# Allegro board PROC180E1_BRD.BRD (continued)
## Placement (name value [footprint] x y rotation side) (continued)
R83  4.7K  [RES0201_0-5]  121.76 149.17 180 top
R84  0E  [RES0201_0-5]  94.58 148.86 180 top
R85  4.7K  [RES0201_0-5]  121.76 148.22 0 top
R86  0E  [RES0805_0-75]  29.53 148.16 0 top
R87  0E  [RES0201_0-5]  73.69 147.95 270 top
R88  59E_1%  [RES0402_0-5]  36.77 147.8 270 top
R89  0E  [RES0201_0-5]  120.92 147.23 180 top
R90  10K  [RES0402_0-5]  92.73 147.17 180 top
R91  10K  [RES0201_0-5]  30.21 146.57 180 top
R92  0E  [RES0603_0-75]  78.61 146.43 0 top
R93  59E_1%  [RES0402_0-5]  36.77 145.55 270 top
R94  10K  [RES0201_0-5]  80.35 143.84 180 top
R95  0E  [RES0201_0-5]  120.24 143.24 90 top
R96  100K  [RES0201_0-5]  40.88 143.04 0 top
R97  0E  [RES0603_0-75]  118.92 142.49 270 top
R98  10K  [RES0201_0-5]  84.24 142.24 270 top
R99  0E  [RES0201_0-5]  79.02 141.96 270 top
R100  0E  [RES0201_0-5]  80.25 141.96 90 top
R101  0E  [RES0201_0-5]  81.14 141.96 90 top
R102  0E  [RES0402_0-5]  40.68 141.72 180 top
R103  10K  [RES0402_0-5]  28.28 141.3 90 top
R104  0E  [RES0201_0-5]  72.54 140.22 270 top
R105  0E  [RES0201_0-5]  73.43 140.22 270 top
R106  10K  [RES0201_0-5]  108.51 138.55 270 top
R107  10K  [RES0201_0-5]  104.22 138.39 180 top
R108  0E  [RES0201_0-5]  109.46 137.76 90 top
R109  0E  [RES0201_0-5]  78.52 136.07 270 top
R110  500E_1%  [RES0402_0-5]  79.78 135.94 270 top
R111  100K_1%  [RES0402_0-5]  81.05 135.94 270 top
R112  10K  [RES0201_0-5]  94.05 134.35 0 top
R113  28K_1%  [RES0402_0-5]  80.45 134.25 180 top
R114  10K  [RES0402_0-5]  57.41 130.66 180 top
R115  100K  [RES0201_0-5]  61.32 127.63 180 top
R116  0E  [RES0201_0-5]  60.72 126.5 0 top
R117  10K  [RES0201_0-5]  65.87 124.88 270 top
R118  4.7K  [RES0201_0-5]  109.22 124.29 90 top
R119  4.7K  [RES0201_0-5]  110.49 124.29 90 top
R120  2.2K  [RES0201_0-5]  41.96 123.04 180 top
R121  0E  [RES0201_0-5]  95.1 121.5 0 top
R122  10K  [RES0201_0-5]  96.31 121.22 270 top
R123  10K  [RES0201_0-5]  74.57 121.03 90 top
R124  10K  [RES0201_0-5]  101.21 119.31 270 top
R125  0E  [RES0201_0-5]  74.57 118.94 270 top
R126  1K  [RES0201_0-5]  91.49 117.43 90 top
R127  1K  [RES0201_0-5]  92.76 117.43 90 top
R128  1K  [RES0201_0-5]  94.03 117.43 90 top
R129  1K  [RES0201_0-5]  95.3 117.43 90 top
R130  1K  [RES0201_0-5]  96.57 117.43 90 top
R131  1K  [RES0201_0-5]  97.84 117.43 90 top
R132  1K  [RES0201_0-5]  99.11 117.43 90 top
R133  1K  [RES0201_0-5]  100.38 117.43 90 top
R134  1K  [RES0201_0-5]  104 117.43 90 top
R135  1K  [RES0201_0-5]  105.27 117.43 90 top
R136  1K  [RES0201_0-5]  106.54 117.43 90 top
R137  1K  [RES0201_0-5]  107.81 117.43 90 top
R138  1K  [RES0201_0-5]  109.08 117.43 90 top
R139  1K  [RES0201_0-5]  110.35 117.43 90 top
R140  1K  [RES0201_0-5]  111.62 117.43 90 top
R141  1K  [RES0201_0-5]  112.89 117.43 90 top
R142  10K  [RES0201_0-5]  75.83 113.62 180 top
R143  10K  [RES0201_0-5]  69.87 111.84 180 top
R144  10K  [RES0201_0-5]  57.19 108.43 0 top
R145  100K  [RES0201_0-5]  91.49 105.99 270 top
R146  100K  [RES0201_0-5]  92.76 105.99 270 top
R147  100K  [RES0201_0-5]  94.03 105.99 270 top
R148  100K  [RES0201_0-5]  95.3 105.99 270 top
R149  100K  [RES0201_0-5]  96.57 105.99 270 top
R150  100K  [RES0201_0-5]  97.84 105.99 270 top
R151  100K  [RES0201_0-5]  99.11 105.99 270 top
R152  100K  [RES0201_0-5]  100.38 105.99 270 top
R153  100K  [RES0201_0-5]  104 105.99 270 top
R154  100K  [RES0201_0-5]  105.27 105.99 270 top
R155  100K  [RES0201_0-5]  106.54 105.99 270 top
R156  100K  [RES0201_0-5]  107.81 105.99 270 top
R157  100K  [RES0201_0-5]  109.08 105.99 270 top
R158  100K  [RES0201_0-5]  110.35 105.99 270 top
R159  100K  [RES0201_0-5]  111.62 105.99 270 top
R160  100K  [RES0201_0-5]  112.89 105.99 270 top
R161  10K  [RES0201_0-5]  95.45 104.42 180 top
R162  10K  [RES0201_0-5]  83.61 104.04 180 top
R163  0E  [RES0201_0-5]  87.2 101.01 90 top
R164  10K  [RES0402_0-5]  51.31 100.68 90 top
R165  0E  [RES0201_0-5]  75.12 99.73 0 top
R166  10K  [RES0201_0-5]  44.91 99.09 90 top
R167  0E  [RES0402_0-5]  65.65 98.89 90 top
R168  0E  [RES0402_0-5]  67.18 98.89 90 top
R169  0E  [RES0402_0-5]  68.7 98.89 90 top
R170  0E  [RES0201_0-5]  49.11 98.71 270 top
R171  0E  [RES0402_0-5]  55.22 98.5 90 top
R172  22E  [RES0402_0-5]  56.74 98.5 90 top
R173  0E  [RES0402_0-5]  58.27 98.5 90 top
R174  22E  [RES0402_0-5]  59.79 98.5 90 top
R175  22E  [RES0201_0-5]  48.83 98.43 0 top
R176  0E  [RES0402_0-5]  77.22 97.62 90 top
R177  0E  [RES0402_0-5]  78.74 97.62 90 top
R178  22E  [RES0402_0-5]  80.27 97.62 270 top
R179  22E  [RES0402_0-5]  81.79 97.62 270 top
R180  220E  [RES0402_0-5]  118.58 97.17 180 top
R181  0E  [RES0201_0-5]  23.27 97.12 0 top
R182  0E  [RES0402_0-5]  64.94 96.86 90 top
R183  0E  [RES0402_0-5]  66.46 96.86 90 top
R184  22E  [RES0402_0-5]  67.99 96.86 90 top
R185  22E  [RES0402_0-5]  70.38 96.65 90 top
R186  0E  [RES0402_0-5]  56.01 96.53 90 top
R187  0E  [RES0402_0-5]  57.53 96.53 90 top
R188  0E  [RES0402_0-5]  59.06 96.53 90 top
R189  0E  [RES0402_0-5]  60.58 96.53 90 top
R190  0E  [RES0402_0-5]  76.48 95.58 90 top
R191  0E  [RES0402_0-5]  78 95.58 90 top
R192  0E  [RES0402_0-5]  79.53 95.58 90 top
R193  0E  [RES0402_0-5]  81.05 95.58 90 top
R194  0E  [RES0201_0-5]  22.28 95.25 90 top
R195  22E  [RES0402_0-5]  46.26 95.22 90 top
R196  10K  [RES0201_0-5]  27.15 95.1 0 top
R197  0E  [RES0402_0-5]  75.51 94.43 270 top
R198  4.7K  [RES0201_0-5]  62.97 94.39 0 top
R199  33E  [RES0402_0-5]  43.56 94.17 180 top
R200  4.7K  [RES0201_0-5]  47.15 94.07 270 top
R201  0E  [RES0402_0-5]  86.44 94.06 90 top
R202  10K  [RES0201_0-5]  68.78 94.01 90 top
R203  10K  [RES0201_0-5]  123.2 93.82 270 top
R204  0E  [RES0201_0-5]  45.98 93.79 180 top
R205  0E  [RES0201_0-5]  70.96 93.74 270 top
R206  0E  [RES0201_0-5]  71.93 93.74 270 top
R207  0E  [RES0201_0-5]  68.78 93.45 270 top
R208  59E_1%  [RES0402_0-5]  33.79 93.33 270 top
R209  0E  [RES0402_0-5]  89.15 92.99 90 top
R210  62E_1%  [RES0402_0-5]  53.06 92.79 0 top
R211  10K  [RES0201_0-5]  103.45 92.71 270 top
R212  10K  [RES0201_0-5]  104.21 92.71 270 top
R213  0E  [RES0402_0-5]  122.47 92.38 180 top
R214  1K  [RES0201_0-5]  91.06 91.65 270 top
R215  59E_1%  [RES0402_0-5]  33.79 91.2 270 top
R216  22E  [RES0201_0-5]  50.26 90.69 180 top
R217  1K  [RES0201_0-5]  91.06 89.82 90 top
R218  4.87K_1%  [RES0402_0-5]  122.05 89.75 90 top
R219  0E  [RES0201_0-5]  106.79 89.39 0 top
R220  10K  [RES0201_0-5]  104.7 89.23 180 top
R221  0E  [RES0201_0-5]  116.3 88.99 180 top
R222  100K  [RES0201_0-5]  36.43 88.62 0 top
R223  0E  [RES0402_0-5]  38.55 88.62 0 top
R224  0E  [RES0201_0-5]  106.79 88.5 0 top
R225  10K  [RES0201_0-5]  103.46 88.26 180 top
R226  10K  [RES0201_0-5]  93.78 88.17 180 top
R227  0E  [RES0201_0-5]  116.3 88.1 180 top
R228  0E  [RES0201_0-5]  89.11 87.73 0 top
R229  1K_1%  [RES0402_0-5]  118.19 87.66 270 top
R230  1K_1%  [RES0402_0-5]  119.46 87.66 270 top
R231  1K_1%  [RES0402_0-5]  120.73 87.66 270 top
R232  1K_1%  [RES0402_0-5]  122 87.66 270 top
R233  0E  [RES0201_0-5]  106.79 87.61 0 top
R234  62E_1%  [RES0402_0-5]  53.96 87.46 0 top
R235  0E  [RES0201_0-5]  116.3 87.21 180 top
R236  4.7K  [RES0201_0-5]  127.8 86.78 270 top
R237  4.7K  [RES0201_0-5]  128.56 86.78 270 top
R238  4.7K  [RES0201_0-5]  100.43 86.64 90 top
R239  0E  [RES0201_0-5]  88.49 85.72 270 top
R240  10K  [RES0201_0-5]  40.63 85.32 270 top
R241  4.7K  [RES0201_0-5]  134.75 85.23 90 top
R242  10K  [RES0201_0-5]  99.84 85.1 0 top
R243  0E  [RES0402_0-5]  53.27 84.63 0 top
R244  10K  [RES0201_0-5]  47.35 83.57 90 top
R245  100K  [RES0402_0-5]  46.28 83.36 90 top
R246  49.9E_1%  [RES0402_0-5]  114.55 83.13 180 top
R247  10K  [RES0201_0-5]  94.65 83.11 180 top
R248  10K  [RES0201_0-5]  25.41 81.49 0 top
R249  0E  [RES0201_0-5]  59.07 81.16 270 top
R250  0E  [RES0201_0-5]  35.29 81.14 180 top
R251  0.01E_1%  [RES_KRL3216T4_1206-4_0-7]  49.35 81.13 90 top
R252  0E  [RES0201_0-5]  58.79 80.94 0 top
R253  0E  [RES0201_0-5]  58.79 79.84 0 top
R254  0E  [RES0201_0-5]  59.07 79.56 90 top
R255  100K_1%  [RES0402_0-5]  42.22 79.51 180 top
R256  62E_1%  [RES0402_0-5]  23.74 79.46 0 top
R257  0E  [RES0402_0-5]  44.16 79.15 0 top
R258  182K_1%  [RES0402_0-5]  40.53 79.02 270 top
R259  4.7K  [RES0201_0-5]  22.88 78.44 0 top
R260  220E  [RES0402_0-5]  23.2 76.87 180 top
R261  0E  [RES0201_0-5]  59.75 76.6 270 top
R262  10K  [RES0201_0-5]  92.87 76.48 0 top
R263  10K  [RES0201_0-5]  92.87 75.72 0 top
R264  10K  [RES0201_0-5]  92.87 74.95 0 top
R265  0.001E_1%  [RES_CST0612_0612-4_0-9]  44.43 74.3 270 top
R266  10K  [RES0201_0-5]  92.87 74.19 0 top
R267  10K  [RES0201_0-5]  92.87 73.43 0 top
R268  10K  [RES0201_0-5]  32.34 72.73 270 top
R269  10K  [RES0201_0-5]  92.87 72.67 0 top
R270  10K  [RES0201_0-5]  92.87 71.91 0 top
R271  0E  [RES0201_0-5]  115.92 71.79 180 top
R272  1K  [RES0402_0-5]  25.8 71.76 270 top
R273  0E  [RES0402_0-5]  62.49 71.57 90 top
R274  0E  [RES0201_0-5]  32.34 71.31 90 top
R275  10K  [RES0201_0-5]  92.87 71.14 0 top
R276  220E  [RES0402_0-5]  135.3 71.01 270 top
R277  1K  [RES0402_0-5]  111.87 70.45 180 top
R278  10K  [RES0201_0-5]  113.58 70.45 180 top
R279  10K  [RES0201_0-5]  31.57 69.98 0 top
R280  10K  [RES0201_0-5]  115.71 68.66 180 top
R281  0E  [RES0201_0-5]  54.94 68.49 270 top
R282  10K  [RES0201_0-5]  55.73 68.49 270 top
R283  0E  [RES0201_0-5]  112.17 68.37 0 top
R284  62E_1%  [RES0402_0-5]  33.27 67.93 90 top
R285  10K  [RES0201_0-5]  112.17 67.61 180 top
R286  0E  [RES0201_0-5]  38.84 67.6 90 top
R287  220E  [RES0402_0-5]  132.7 67.24 270 top
R288  10K  [RES0201_0-5]  57.09 67.08 0 top
R289  20K_1%  [RES0402_0-5]  134.48 67.04 0 top
R290  0E  [RES0201_0-5]  55.09 66.8 270 top
R291  10K  [RES0201_0-5]  55.88 66.8 270 top
R292  220E  [RES0402_0-5]  37.76 66.41 0 top
R293  0E  [RES0201_0-5]  29.35 65.96 0 top
R294  0E  [RES0201_0-5]  43.51 65.79 0 top
R295  30K  [RES0402_0-5]  134.48 65.77 180 top
R296  0E  [RES0201_0-5]  41.48 65.34 0 top
R297  0E  [RES0201_0-5]  42.67 64.61 270 top
R298  2K_1%  [RES0402_0-5]  34.68 64.52 90 top
R299  0E  [RES0201_0-5]  55.63 64.46 90 top
R300  0E  [RES0201_0-5]  56.41 64.46 90 top
R301  4.7K  [RES0201_0-5]  38.47 64.36 270 top
R302  10K  [RES0402_0-5]  20.69 64.2 90 top
R303  1.3K_1%  [RES0402_0-5]  28.96 64.06 180 top
R304  0E  [RES0603_0-75]  61.56 64.03 180 top
R305  0E  [RES0201_0-5]  36.83 63.64 0 top
R306  51K_1%  [RES0402_0-5]  116.42 63.25 0 top
R307  0E  [RES0201_0-5]  41.24 63.14 90 top
R308  1K_1%  [RES0402_0-5]  35.78 62.53 270 top
R309  100K  [RES0402_0-5]  20.09 62.4 180 top
R310  0E  [RES0402_0-5]  55.51 62.36 270 top
R311  0E  [RES0402_0-5]  56.66 62.36 270 top
R312  240E_1%  [RES0201_0-5]  66.97 62.03 0 top
R313  30K_1%  [RES0402_0-5]  116.42 61.98 180 top
R314  0E  [RES0201_0-5]  120.42 60.56 90 top
R315  240E_1%  [RES0201_0-5]  66.97 59.63 0 top
R316  0.01E_1%  [RES_KRL3216T4_1206-4_0-7]  56.18 59.2 0 top
R317  0E  [RES0201_0-5]  48.44 58.81 180 top
R318  10K  [RES0402_0-5]  26.62 58.34 180 top
R319  0E  [RES0201_0-5]  59.89 56.26 90 top
R320  10K  [RES0201_0-5]  60.91 56.26 270 top
R321  10K  [RES0201_0-5]  28.14 53.12 90 top
R322  4.7K  [RES0201_0-5]  35.69 52.75 180 top
R323  2.2K  [RES0201_0-5]  29.16 52.56 90 top
R324  220E  [RES0402_0-5]  34.39 88.62 0 top
R325  10K  [RES0201_0-5]  71.14 51.98 0 top
R326  4.7K  [RES0201_0-5]  35.69 51.92 180 top
R327  0.001E_1%  [RES_CST0612_0612-4_0-9]  57.15 51.75 0 top
R328  10K  [RES0201_0-5]  28.44 51.54 0 top
R329  10K  [RES0201_0-5]  80.97 51.22 0 top
R330  220E  [RES0402_0-5]  30.92 50.49 0 top
R331  0E  [RES0402_0-5]  48.97 50.29 180 top
R332  0E  [RES0402_0-5]  74.29 50.27 90 top
R333  10K  [RES0201_0-5]  28.14 50.07 180 top
R334  0.01E_1%  [RES_KRL3216T4_1206-4_0-7]  45.08 49.68 270 top
R335  0E  [RES0402_0-5]  48.97 49.02 180 top
R336  22E  [RES0201_0-5]  78.09 48.58 0 top
R337  0E  [RES0201_0-5]  78.09 47.82 0 top
R338  0E  [RES0402_0-5]  85.25 47.62 180 top
R339  10K  [RES0201_0-5]  69.44 47.24 0 top
R340  0E  [RES0402_0-5]  88.07 47 180 top
R341  1K_1%  [RES0402_0-5]  122.28 46.89 0 top
R342  10K  [RES0201_0-5]  84.77 46.57 180 top
R343  1.5K  [RES0201_0-5]  86.32 46.57 180 top
R344  2.2K  [RES0201_0-5]  116 46.49 0 top
R345  0E  [RES0201_0-5]  119.68 46.49 0 top
R346  0E  [RES0201_0-5]  117.52 46.48 0 top
R347  100K  [RES0201_0-5]  128.93 46.48 270 bottom
R348  10K  [RES0201_0-5]  70.72 46.33 90 top
R349  22E  [RES0201_0-5]  69.56 46.32 90 top
R350  0E  [RES0402_0-5]  72.76 46.25 90 top
R351  1.5K  [RES0201_0-5]  119.68 45.6 180 top
R352  0E  [RES0201_0-5]  118.51 45.29 270 top
R353  100K  [RES0201_0-5]  87.64 45 270 top
R354  100K  [RES0201_0-5]  121.02 44.99 270 top
R355  1K_1%  [RES0402_0-5]  89.46 44.56 270 top
R356  10K  [RES0201_0-5]  118.79 44.03 180 top
R357  10K  [RES0201_0-5]  23.04 42.28 0 top
R358  22E  [RES0201_0-5]  67.66 37.43 180 top
R359  22E  [RES0201_0-5]  71.11 37.11 270 top
R360  100K  [RES0201_0-5]  73.28 36.76 270 top
R361  4.7K  [RES0201_0-5]  28.19 34.68 180 top
R362  10K  [RES0201_0-5]  67.82 31.96 0 top
R363  10K  [RES0201_0-5]  69.53 31.96 180 top
R364  0E  [RES0201_0-5]  66.52 31.36 270 top
R365  10K  [RES0201_0-5]  71.28 31.16 90 top
R366  0E  [RES0201_0-5]  70.13 30.98 180 top
R367  10K  [RES0201_0-5]  67.32 30.8 270 top
R368  10K  [RES0201_0-5]  45.21 30.41 270 top
R369  10K  [RES0201_0-5]  45.98 30.41 90 top
R370  10K  [RES0201_0-5]  46.94 30.41 90 top
R371  10K  [RES0201_0-5]  51.17 30.37 0 top
R372  10K  [RES0201_0-5]  67.32 29.33 270 top
R373  10K  [RES0201_0-5]  68.72 28.81 180 top
R374  10K  [RES0201_0-5]  43.91 28.51 270 top
R375  10K  [RES0201_0-5]  63.82 27.9 180 top
R376  0E  [RES0201_0-5]  68.73 27.84 180 top
R377  0E  [RES0201_0-5]  70.17 27.84 0 top
R378  10K  [RES0201_0-5]  35.34 27.09 90 top
R379  0E  [RES0201_0-5]  58.79 26.02 270 top
R380  10K  [RES0201_0-5]  48.56 25.62 270 top
R381  10K  [RES0201_0-5]  26.52 25.07 90 top
R382  0E  [RES0201_0-5]  25.68 24.91 90 top
R383  10K  [RES0201_0-5]  58.51 24.85 180 top
R384  16.5K_1%  [RES0402_0-5]  69.69 24.34 0 top
R385  0E  [RES0805_0-75]  12.55 24.33 90 top
R386  0E  [RES0201_0-5]  25.95 23.8 0 top
R387  10K  [RES0201_0-5]  46.15 23.75 180 top
R388  0E  [RES0201_0-5]  47.2 23.47 270 top
R389  3.48K_1%  [RES0201_0-5]  69.9 22.95 180 top
R390  0E  [RES0201_0-5]  24.41 22.56 0 top
R391  130K_1%  [RES0402_0-5]  47.74 21.36 180 top
R392  680K_1%  [RES0402_0-5]  49.45 20.87 90 top
R393  0E  [RES0402_0-5]  64.65 20.11 270 top
R394  0E  [RES0402_0-5]  65.5 20.11 270 top
R395  0E  [RES0603_0-75]  29.41 19.14 0 top
R396  10K  [RES0201_0-5]  57.2 18.68 270 top
R397  470E  [RES0402_0-5]  35.15 15.24 90 top
R398  16.5K_1%  [RES0402_0-5]  53.31 12.95 270 top
R399  0E  [RES0402_0-5]  48.97 12.17 270 top
R400  0E  [RES0402_0-5]  49.82 12.17 270 top
R401  3.48K_1%  [RES0201_0-5]  53.03 11.57 180 top
R402  470E  [RES0402_0-5]  45.06 10.86 90 top
R403  0E  [RES0603_0-75]  42.58 8.45 90 top
R404  0E  [RES0603_0-75]  27.81 8.39 90 top
R405  4.3K  [RES0402_0-5]  90.34 179.93 270 bottom
R406  4.3K  [RES0402_0-5]  89.07 179.93 270 bottom
R407  4.3K  [RES0402_0-5]  86.5 179.93 270 bottom
R408  4.3K  [RES0402_0-5]  85.23 179.93 270 bottom
R409  4.3K  [RES0402_0-5]  73.2 179.93 270 bottom
R410  4.3K  [RES0402_0-5]  71.93 179.93 270 bottom
R411  4.3K  [RES0402_0-5]  69.36 179.93 270 bottom
R412  4.3K  [RES0402_0-5]  68.09 179.93 270 bottom
R413  10K  [RES0402_0-5]  80.85 174.25 180 bottom
R414  0E  [RES0201_0-5]  82.72 172.98 180 bottom
R415  10K  [RES0402_0-5]  76.16 171.56 270 bottom
R416  10K  [RES0402_0-5]  77.56 171.55 90 bottom
R417  10K  [RES0201_0-5]  47.17 168.06 0 bottom
R418  1K  [RES0402_0-5]  133.23 166.02 270 bottom
R419  1K  [RES0402_0-5]  131.94 166.02 90 bottom
R420  0E  [RES0201_0-5]  130.05 163.79 0 bottom
R421  0E  [RES0201_0-5]  112.53 163.78 0 bottom
R422  1K  [RES0402_0-5]  132.92 163.76 90 bottom
R423  1K  [RES0402_0-5]  131.61 163.76 270 bottom
R424  10K  [RES0201_0-5]  47.01 163.55 90 bottom
R425  10K  [RES0201_0-5]  45.06 163.08 90 bottom
R426  10K  [RES0201_0-5]  43.97 163.08 90 bottom
R427  0E  [RES0201_0-5]  52.99 162.99 180 bottom
R428  0E  [RES0201_0-5]  55.53 161.84 0 bottom
R429  10K  [RES0201_0-5]  105.57 161.26 180 bottom
R430  10K  [RES0201_0-5]  124.04 161.09 180 bottom
R431  0E  [RES0201_0-5]  75.21 159.73 180 bottom
R432  0E  [RES0201_0-5]  73.73 159.35 270 bottom
R433  0E  [RES0201_0-5]  74.01 159.07 180 bottom
R434  10K  [RES0201_0-5]  53.08 158.86 180 bottom
R435  0E  [RES0201_0-5]  73.73 158.79 90 bottom
R436  10K  [RES0402_0-5]  42.43 155.13 270 bottom
R437  2.2K  [RES0201_0-5]  108.85 151.32 0 bottom
R438  1K  [RES0201_0-5]  93.16 140.06 0 bottom
R439  10K  [RES0201_0-5]  93.16 137.52 180 bottom
R440  220E  [RES0402_0-5]  48.11 129 0 bottom
R441  0E  [RES0402_0-5]  53.89 125.16 180 bottom
R442  10K  [RES0201_0-5]  51.85 125.16 0 bottom
R443  10K  [RES0201_0-5]  81.22 123.25 90 bottom
R444  10K  [RES0201_0-5]  80.22 123.25 90 bottom
R445  10K  [RES0201_0-5]  79.22 123.25 90 bottom
R446  10K  [RES0201_0-5]  78.65 122 135 bottom
R447  10K  [RES0201_0-5]  82.79 121.62 90 bottom
R448  10K  [RES0201_0-5]  76.26 121.33 90 bottom
R449  10K  [RES0201_0-5]  77.49 120.98 180 bottom
R450  10K  [RES0201_0-5]  79.75 120.55 270 bottom
R451  10K  [RES0201_0-5]  82.79 120.39 90 bottom
R452  10K  [RES0201_0-5]  77.5 120.21 180 bottom
R453  22E  [RES0201_0-5]  79.98 119.41 0 bottom
R454  10K  [RES0201_0-5]  80.54 118.71 0 bottom
R455  10K  [RES0201_0-5]  70.33 118.1 180 bottom
R456  10K  [RES0201_0-5]  105.38 116.15 180 bottom
R457  10K  [RES0201_0-5]  110.49 115.98 0 bottom
R458  10K  [RES0201_0-5]  78.2 115.81 90 bottom
R459  10K  [RES0201_0-5]  77.31 115.81 270 bottom
R460  10K  [RES0201_0-5]  76.42 115.81 270 bottom
R461  10K  [RES0201_0-5]  102.57 114.67 0 bottom
R462  10K  [RES0201_0-5]  70.67 113.34 90 bottom
R463  0E  [RES0201_0-5]  73.28 110.33 180 bottom
R464  4.7K  [RES0201_0-5]  17.22 109.45 0 bottom
R465  4.7K  [RES0201_0-5]  17.25 108.66 0 bottom
R466  0E  [RES0402_0-5]  72.75 108.31 0 bottom
R467  10K  [RES0201_0-5]  59.64 108.1 180 bottom
R468  0E  [RES0201_0-5]  70.04 107.62 0 bottom
R469  10K  [RES0201_0-5]  59.09 107.34 0 bottom
R470  0E  [RES0402_0-5]  72.76 107.16 0 bottom
R471  10K  [RES0201_0-5]  59.09 106.42 0 bottom
R472  0E  [RES0201_0-5]  69.99 105.71 0 bottom
R473  10K  [RES0201_0-5]  59.09 105.53 0 bottom
R474  0E  [RES0201_0-5]  74.72 105.2 0 bottom
R475  0E  [RES0201_0-5]  74.72 104.54 0 bottom
R476  33E  [RES0201_0-5]  113.29 104.09 90 bottom
R477  0E  [RES0201_0-5]  76.97 104.05 90 bottom
R478  0E  [RES0201_0-5]  77.75 104.04 90 bottom
R479  0E  [RES0201_0-5]  78.53 104.03 90 bottom
R480  10K  [RES0201_0-5]  109.17 103.84 90 bottom
R481  0E  [RES0201_0-5]  66.31 103.81 90 bottom
R482  4.7K  [RES0201_0-5]  105.93 103.62 90 bottom
R483  33E  [RES0201_0-5]  118.11 103.56 270 bottom
R484  0E  [RES0201_0-5]  64.61 103.24 0 bottom
R485  10K  [RES0201_0-5]  114.99 103.01 90 bottom
R486  0E  [RES0201_0-5]  75.35 101.93 0 bottom
R487  100E_1%  [RES0402_0-5]  114.99 101.28 270 bottom
R488  10K  [RES0201_0-5]  69.16 100.18 90 bottom
R489  10K  [RES0201_0-5]  116.71 99.04 270 bottom
R490  0E  [RES0201_0-5]  115.51 99.04 270 bottom
R491  0E  [RES0402_0-5]  82.91 97.46 90 bottom
R492  0E  [RES0402_0-5]  81.34 97.46 90 bottom
R493  0E  [RES0402_0-5]  79.76 97.46 90 bottom
R494  0E  [RES0402_0-5]  78.19 97.46 90 bottom
R495  0E  [RES0402_0-5]  76.69 97.46 90 bottom
R496  0E  [RES0402_0-5]  67.18 96.8 180 bottom
R497  0E  [RES0402_0-5]  83.55 95.49 90 bottom
R498  0E  [RES0402_0-5]  82.03 95.49 90 bottom
R499  0E  [RES0402_0-5]  80.5 95.49 90 bottom
R500  0E  [RES0402_0-5]  78.98 95.49 90 bottom
R501  0E  [RES0402_0-5]  77.45 95.49 90 bottom
R502  0E  [RES0402_0-5]  75.93 95.49 90 bottom
R503  4.7K  [RES0201_0-5]  61.08 94.63 180 bottom
R504  1K  [RES0201_0-5]  75.28 93.1 90 bottom
R505  0E  [RES0201_0-5]  50.11 92.84 90 bottom
R506  0E  [RES0402_0-5]  72.3 90.88 90 bottom
R507  10K  [RES0201_0-5]  106.79 89.39 180 bottom
R508  4.7K  [RES0201_0-5]  59.71 89.39 0 bottom
R509  0E  [RES0201_0-5]  88.78 89.35 0 bottom
R510  10K  [RES0201_0-5]  114.08 89.28 180 bottom
R511  10K  [RES0201_0-5]  116.3 88.99 0 bottom
R512  10K  [RES0201_0-5]  108.99 88.9 0 bottom
R513  10K  [RES0201_0-5]  106.79 88.5 180 bottom
R514  22E  [RES0402_0-5]  59.71 88.5 180 bottom
R515  10K  [RES0201_0-5]  114.08 88.48 180 bottom
R516  10K  [RES0201_0-5]  116.3 88.1 0 bottom
R517  10K  [RES0201_0-5]  108.99 88.1 0 bottom
R518  0E  [RES0201_0-5]  87.12 87.92 0 bottom
R519  10K  [RES0201_0-5]  114.08 87.68 180 bottom
R520  1K_1%  [RES0402_0-5]  122 87.66 90 bottom
R521  1K_1%  [RES0402_0-5]  120.73 87.66 90 bottom
R522  1K_1%  [RES0402_0-5]  119.46 87.66 90 bottom
R523  1K_1%  [RES0402_0-5]  118.19 87.66 90 bottom
R524  10K  [RES0201_0-5]  106.79 87.61 180 bottom
R525  10K  [RES0201_0-5]  108.99 87.3 0 bottom
R526  10K  [RES0201_0-5]  116.3 87.21 0 bottom
R527  0E  [RES0201_0-5]  87.12 87.05 0 bottom
R528  0E  [RES0201_0-5]  87.12 86.28 0 bottom
R529  0E  [RES0201_0-5]  90.17 86 0 bottom
R530  0E  [RES0201_0-5]  87.12 85.43 0 bottom
R531  10K  [RES0201_0-5]  116.93 84.93 270 bottom
R532  10K  [RES0201_0-5]  28.47 84.16 0 bottom
R533  10K  [RES0201_0-5]  119.53 84.08 180 bottom
R534  10K  [RES0201_0-5]  118.39 84.07 90 bottom
R535  0E  [RES0201_0-5]  87.05 83.98 0 bottom
R536  10K  [RES0201_0-5]  117.21 83.89 0 bottom
R537  0E  [RES0201_0-5]  83.78 83.84 0 bottom
R538  0E  [RES0201_0-5]  66.91 83.74 180 bottom
R539  0E  [RES0402_0-5]  49.93 83.22 270 bottom
R540  0E  [RES0402_0-5]  48.79 83.22 270 bottom
R541  0E  [RES0402_0-5]  86.14 82.88 0 bottom
R542  22E  [RES0201_0-5]  67.18 82.82 0 bottom
R543  10K_1%  [RES0201_0-5]  58.69 82.71 0 bottom
R544  22E  [RES0201_0-5]  118.58 82.64 270 bottom
R545  1.1K_1%  [RES0402_0-5]  60.36 82.22 270 bottom
R546  4.7K  [RES0201_0-5]  35.5 82.21 90 bottom
R547  4.7K  [RES0201_0-5]  34.57 82.21 90 bottom
R548  0E  [RES0402_0-5]  86.15 81.6 0 bottom
R549  10K  [RES0201_0-5]  117.74 80.93 180 bottom
R550  10K  [RES0201_0-5]  34.82 80.7 180 bottom
R551  4.7K  [RES0201_0-5]  129.69 80.35 270 bottom
R552  4.7K  [RES0201_0-5]  128.8 80.35 270 bottom
R553  499E_1%  [RES0402_0-5]  82.21 79.95 0 bottom
R554  10K  [RES0201_0-5]  118.42 79.83 270 bottom
R555  10K  [RES0201_0-5]  119.34 79.82 90 bottom
R556  10K  [RES0201_0-5]  117.5 79.82 270 bottom
R557  499E_1%  [RES0402_0-5]  85.05 79.6 90 bottom
R558  0E  [RES0201_0-5]  87.33 78.44 180 bottom
R559  10K  [RES0201_0-5]  28.47 77.3 0 bottom
R560  10K_1%  [RES0201_0-5]  81.56 77.04 0 bottom
R561  10K  [RES0201_0-5]  103.36 76.53 0 bottom
R562  10K  [RES0201_0-5]  100.6 76.08 90 bottom
R563  0E  [RES0201_0-5]  65.45 76.04 0 bottom
R564  4.7K  [RES0201_0-5]  124.44 75.58 90 bottom
R565  10K  [RES0201_0-5]  103.36 75.57 180 bottom
R566  22E  [RES0201_0-5]  125.26 75.56 270 bottom
R567  10K_1%  [RES0201_0-5]  81.56 75.44 0 bottom
R568  1M  [RES0402_0-5]  58.6 75.39 90 bottom
R569  10K  [RES0201_0-5]  123.15 75.23 0 bottom
R570  0E  [RES0201_0-5]  61.17 74.78 90 bottom
R571  0E  [RES0402_0-5]  38.5 73.69 90 bottom
R572  0E  [RES0402_0-5]  37.24 73.67 90 bottom
R573  240E_1%  [RES0201_0-5]  65.77 73.51 90 bottom
R574  22E  [RES0201_0-5]  64.08 73.27 180 bottom
R575  10K  [RES0201_0-5]  102.05 72.86 180 bottom
R576  100E_1%  [RES0402_0-5]  116.38 71.72 0 bottom
R577  0E  [RES0603_0-75]  53.71 71.38 0 bottom
R578  1K  [RES0402_0-5]  131.74 70.86 0 bottom
R579  0E  [RES0201_0-5]  128.68 70.66 90 bottom
R580  0E  [RES0201_0-5]  129.98 70.63 90 bottom
R581  0.01E_1%  [RES_KRL3216T4_1206-4_0-7]  57.24 70.57 90 bottom
R582  4.7K  [RES0201_0-5]  126.41 69.64 270 bottom
R583  4.7K  [RES0201_0-5]  128.4 69.36 0 bottom
R584  0E  [RES0402_0-5]  59.92 66.27 90 bottom
R585  0E  [RES0402_0-5]  58.78 66.27 90 bottom
R586  0E  [RES0201_0-5]  37.13 64.11 270 bottom
R587  0E  [RES0603_0-75]  52.87 63.13 0 bottom
R588  10K  [RES0402_0-5]  87.05 62.23 270 bottom
R589  2.2K  [RES0402_0-5]  87.05 59.93 270 bottom
R590  10K  [RES0201_0-5]  35.45 58.4 0 bottom
R591  10K  [RES0201_0-5]  35.45 57.51 180 bottom
R592  4.7K  [RES0201_0-5]  36.63 56.75 90 bottom
R593  4.7K  [RES0201_0-5]  36.47 55.76 180 bottom
R594  2.2K  [RES0402_0-5]  77.61 54.32 180 bottom
R595  2.2K  [RES0402_0-5]  73.29 54.32 0 bottom
R596  0E  [RES0201_0-5]  56.06 53.73 270 bottom
R597  10K  [RES0201_0-5]  56.06 52.1 270 bottom
R598  4.7K  [RES0201_0-5]  37.94 50.26 180 bottom
R599  0E  [RES0402_0-5]  53.5 49.74 90 bottom
R600  0E  [RES0402_0-5]  54.8 49.73 90 bottom
R601  10K  [RES0201_0-5]  114.04 49.13 180 bottom
R602  10K  [RES0201_0-5]  112.34 49.13 0 bottom
R603  4.7K  [RES0201_0-5]  37.95 49.02 180 bottom
R604  0E  [RES0201_0-5]  115.65 48.25 180 bottom
R605  0E  [RES0201_0-5]  111.73 48.15 0 bottom
R606  10K  [RES0201_0-5]  114.55 47.97 270 bottom
R607  10K  [RES0201_0-5]  113.15 45.84 0 bottom
R608  0E  [RES0201_0-5]  58.69 45.12 270 bottom
R609  12K_1%  [RES0402_0-5]  26.58 44.48 0 bottom
R610  0E  [RES0805_0-75]  131.94 44.32 0 bottom
R611  4.7K  [RES0201_0-5]  30.38 44 180 bottom
R612  4.7K  [RES0201_0-5]  31.82 43.89 270 bottom
R613  10K  [RES0201_0-5]  29.2 43.69 270 bottom
R614  10K  [RES0201_0-5]  28.32 43.69 90 bottom
R615  10K  [RES0201_0-5]  63 43.18 0 bottom
R616  10K  [RES0402_0-5]  127.05 41.7 0 bottom
R617  1K  [RES0402_0-5]  56.33 41.16 90 bottom
R618  1K  [RES0402_0-5]  127.05 40.43 180 bottom
R619  0E  [RES0201_0-5]  53.22 40.26 270 bottom
R620  2.2K  [RES0201_0-5]  82.72 39.8 270 bottom
R621  0E  [RES0201_0-5]  83.53 39.79 90 bottom
R622  10K  [RES0402_0-5]  123.38 39.53 0 bottom
R623  0E  [RES0201_0-5]  96.15 39.1 180 bottom
R624  0E  [RES0201_0-5]  112.71 38.99 0 bottom
R625  1K  [RES0402_0-5]  123.38 38.26 180 bottom
R626  10K  [RES0402_0-5]  70.59 36.31 0 bottom
R627  0E  [RES0201_0-5]  48.29 35.74 180 bottom
R628  1K  [RES0402_0-5]  68.73 35.47 270 bottom
R629  1K  [RES0402_0-5]  72.37 35.44 270 bottom
R630  10K  [RES0402_0-5]  70.64 34.73 0 bottom
R631  4.7K  [RES0201_0-5]  25.57 34.4 270 bottom
R632  100K_1%  [RES0402_0-5]  90.51 34.14 90 bottom
R633  0E  [RES0201_0-5]  48.29 33.2 180 bottom
R634  316K_1%  [RES0402_0-5]  89.24 33.16 90 bottom
R635  10K  [RES0201_0-5]  25.34 32.8 90 bottom
R636  10K  [RES0201_0-5]  26.25 31.94 270 bottom
R637  10K  [RES0201_0-5]  89.21 31.55 180 bottom
R638  10K  [RES0402_0-5]  67.2 31.48 270 bottom
R639  1K  [RES0402_0-5]  69.58 31.08 90 bottom
R640  0E  [RES0201_0-5]  89.2 30.61 0 bottom
R641  10K  [RES0402_0-5]  67.35 29.14 90 bottom
R642  1K  [RES0402_0-5]  69.44 28.89 180 bottom
R643  0E  [RES0805_0-75]  34.42 28.43 0 bottom
R644  10K  [RES0201_0-5]  39.92 26.88 270 bottom
R645  10K  [RES0201_0-5]  39.16 26.88 270 bottom
R646  10K  [RES0201_0-5]  42.61 26.67 180 bottom
R647  0E  [RES0201_0-5]  49.56 26.09 0 bottom
R648  44.2K_1%  [RES0402_0-5]  19.91 26.02 90 bottom
R649  0E  [RES0402_0-5]  21.7 25.64 90 bottom
R650  0E  [RES0402_0-5]  23 25.63 90 bottom
R651  0E  [RES0201_0-5]  42.33 25.5 90 bottom
R652  0E  [RES0201_0-5]  41.57 25.5 90 bottom
R653  0E  [RES0201_0-5]  40.81 25.5 90 bottom
R654  0E  [RES0201_0-5]  40.05 25.5 90 bottom
R655  0E  [RES0201_0-5]  39.29 25.5 270 bottom
R656  0E  [RES0201_0-5]  38.52 25.5 270 bottom
R657  0E  [RES0201_0-5]  37.76 25.5 270 bottom
R658  10K  [RES0201_0-5]  35.26 25.08 270 bottom
R659  0E  [RES0201_0-5]  34.27 25.01 90 bottom
R660  10K  [RES0201_0-5]  36.59 24.77 0 bottom
R661  10K  [RES0402_0-5]  14.58 24.17 180 bottom
R662  100K  [RES0201_0-5]  44.5 23.88 90 bottom
R663  0.005E_1%  [RES1206_1]  32.72 23.84 90 bottom
R664  10K  [RES0201_0-5]  34.91 23.66 270 bottom
R665  0E  [RES0402_0-5]  45.68 22.51 180 bottom
R666  0E  [RES0201_0-5]  49.43 22.09 180 bottom
R667  0E  [RES0201_0-5]  34.51 22.09 180 bottom
R668  10K  [RES0402_0-5]  15.09 21.09 180 bottom
R669  1K  [RES0402_0-5]  46.16 19.69 0 bottom
R670  2.05K_1%  [RES0402_0-5]  15.91 19.15 270 bottom
R671  10E  [RES0402_0-5]  21.47 18.44 180 bottom
R672  100K  [RES0402_0-5]  47.14 18.29 0 bottom
R673  0E  [RES0201_0-5]  45.49 18.29 0 bottom
R674  0E  [RES0201_0-5]  35.03 17.96 0 bottom
R675  10K_1%  [RES0201_0-5]  57.92 17.65 90 bottom
R676  10K_1%  [RES0201_0-5]  50.12 16.56 270 bottom
R677  10K  [RES0201_0-5]  49.7 15.62 180 bottom
R678  0E  [RES0201_0-5]  39.49 15.61 180 bottom
R679  10K_1%  [RES0201_0-5]  40.55 15.24 90 bottom
R680  10K  [RES0201_0-5]  52.39 14.46 180 bottom
R681  100K_1%  [RES0402_0-5]  40.68 13.56 270 bottom
R682  100K_1%  [RES0402_0-5]  39.41 13.56 270 bottom
R683  0E  [RES0603_0-75]  57.56 5.32 180 bottom
RA1  1K  [RESA_EXB_0201-2_0-5]  68.86 106.1 270 top
RA2  1K  [RESA_EXB_0201-2_0-5]  80.72 102.44 180 top
RA3  0E  [RESA_EXB_0201-4_0-5]  71.99 97.07 180 top
RA4  0E  [RESA_EXB_0201-4_0-5]  74.41 97.07 180 top
RA5  1K  [RESA_EXB_0201-4_0-5]  119.26 113.7 90 bottom
RA6  1K  [RESA_EXB_0201-4_0-5]  119.98 105.12 90 bottom
RA7  1K  [RESA_EXB_0201-4_0-5]  80.28 103.5 180 bottom
SW1  416131160808  [SW16_416131160808_460X230_SMD_2-7]  95.94 111.86 0 top
SW2  416131160808  [SW16_416131160808_460X230_SMD_2-7]  108.44 111.86 0 top
SW3  218-2LPST  [SW4_49-99_150X230_SMD_2-7]  96.16 90.73 90 top
SW4  7914G-1-000E  [SW4_100X216_200X200_SMD_4-2]  31.5 84.52 270 top
SW5  7914G-1-000E  [SW4_100X216_200X200_SMD_4-2]  31.5 77.66 270 top
SW6  7914G-1-000E  [SW4_100X216_200X200_SMD_4-2]  64.34 41.26 90 top
SW7  7914G-1-000E  [SW4_100X216_200X200_SMD_4-2]  52.72 34.7 180 top
SW8  7914G-1-000E  [SW4_100X216_200X200_SMD_4-2]  60.8 31.23 270 top
TP1  THRU HOLE  [TP_40X65]  30.7 173.74 0 top
TP2  THRU HOLE  [TP_40X65]  112.98 172.66 0 top
TP3  -  [TP30_SMD]  51.43 170.73 0 top
TP4  -  [TP30_SMD]  51.43 169.29 90 top
TP5  -  [TP30_SMD]  82.45 167.06 90 top
TP6  -  [TP30_SMD]  84.82 166.01 90 top
TP7  -  [TP30_SMD]  52.69 164.82 0 top
TP8  -  [TP30_SMD]  83.34 164.56 270 top
TP9  -  [TP30_SMD]  84.82 164.56 270 top
TP10  -  [TP30_SMD]  51.34 164.05 0 top
TP11  -  [TP30_SMD]  113.13 163.78 180 top
TP12  -  [TP30_SMD]  95.52 163.75 180 top
TP13  -  [TP30_SMD]  52.69 163.29 0 top
TP14  -  [TP30_SMD]  130.32 162.87 180 top
TP15  -  [TP30_SMD]  51.34 162.53 0 top
TP16  -  [TP30_SMD]  38.52 161.85 0 top
TP17  -  [TP30_SMD]  100.35 160.44 180 top
TP18  -  [TP30_SMD]  101.7 160.44 180 top
TP19  -  [TP30_SMD]  117.75 160.44 180 top
TP20  -  [TP30_SMD]  119.1 160.44 180 top
TP21  -  [TP20_SMD]  16.46 159.59 270 top
TP22  -  [TP30_SMD]  101.01 159.22 180 top
TP23  -  [TP30_SMD]  118.41 159.22 180 top
TP24  -  [TP30_SMD]  50.56 157.86 0 top
TP25  -  [TP30_SMD]  65.45 156.51 90 top
TP26  -  [TP30_SMD]  62.12 156.14 90 top
TP27  -  [TP30_SMD]  63.78 156.11 270 top
TP28  -  [TP30_SMD]  45.76 155.46 90 top
TP29  -  [TP30_SMD]  47.21 155.46 0 top
TP30  -  [TP30_SMD]  48.65 155.46 90 top
TP31  -  [TP30_SMD]  69.14 152.43 270 top
TP32  -  [TP30_SMD]  115.29 151.29 270 top
TP33  -  [TP30_SMD]  113.81 151.29 270 top
TP34  -  [TP30_SMD]  73.36 150.7 90 top
TP35  -  [TP20_SMD]  18.86 150.67 90 top
TP36  -  [TP30_SMD]  114.37 148.23 90 top
TP37  -  [TP30_SMD]  114.58 146.24 270 top
TP38  -  [TP30_SMD]  121.39 145.59 270 top
TP39  -  [TP30_SMD]  121.99 143.77 270 top
TP40  THRU HOLE  [TP_40X65]  131.04 142.12 0 top
TP41  -  [TP40_SMD]  88.31 138.91 0 top
TP42  -  [TP40_SMD]  69.06 137.61 0 top
TP43  -  [TP30_SMD]  78.21 134.19 0 top
TP44  -  [TP40_SMD]  92.01 124.54 0 top
TP45  -  [TP20_SMD]  108.66 119.14 180 top
TP46  -  [TP20_SMD]  47.35 92.76 0 top
TP47  -  [TP20_SMD]  55.71 90.75 90 top
TP48  -  [TP20_SMD]  43.19 87.71 90 top
TP49  -  [TP20_SMD]  99.71 86.65 180 top
TP50  -  [TP20_SMD]  35.92 82.77 180 top
TP51  -  [TP20_SMD]  116.04 81.54 90 top
TP52  -  [TP20_SMD]  47.29 78.96 270 top
TP53  -  [TP20_SMD]  90.86 76.51 90 top
TP54  -  [TP20_SMD]  60.45 75.5 180 top
TP55  -  [TP20_SMD]  33.47 72.45 0 top
TP56  -  [TP20_SMD]  56.69 70.43 0 top
TP57  -  [TP20_SMD]  30.53 69.98 180 top
TP58  -  [TP20_SMD]  114.97 69.93 180 top
TP59  -  [TP30_SMD]  27.58 69.82 0 top
TP60  -  [TP20_SMD]  58.48 69.69 90 top
TP61  -  [TP20_SMD]  111.01 69.15 180 top
TP62  -  [TP20_SMD]  117.84 67.92 180 top
TP63  -  [TP20_SMD]  119.92 67.69 180 top
TP64  -  [TP20_SMD]  118.83 67.36 180 top
TP65  -  [TP30_SMD]  24.73 66.87 0 top
TP66  -  [TP20_SMD]  120.53 66.77 180 top
TP67  -  [TP20_SMD]  56.71 66.35 0 top
TP68  -  [TP20_SMD]  115.74 65.99 270 top
TP69  -  [TP20_SMD]  61.07 65.37 270 top
TP70  -  [TP20_SMD]  56.95 65.19 0 top
TP71  -  [TP20_SMD]  127.4 64.98 0 top
TP72  -  [TP30_SMD]  40.27 64.22 90 top
TP73  -  [TP30_SMD]  39.35 63.74 90 top
TP74  -  [TP20_SMD]  42.33 61.53 0 top
TP75  -  [TP20_SMD]  30.25 61.11 0 top
TP76  -  [TP20_SMD]  42.33 60.37 90 top
TP77  THRU HOLE  [TP_40X65]  133.04 60.1 0 top
TP78  -  [TP20_SMD]  124.45 60.08 270 top
TP79  -  [TP20_SMD]  58.24 59.95 0 top
TP80  -  [TP40_SMD]  38.55 59.8 0 top
TP81  -  [TP40_SMD]  51.33 58.21 0 top
TP82  -  [TP20_SMD]  33.44 58.16 0 top
TP83  -  [TP20_SMD]  64.99 57.52 0 top
TP84  -  [TP_CIR40D30]  38.27 57.51 0 top
TP85  THRU HOLE  [TP_40X65]  17.68 56.72 0 top
TP86  -  [TP20_SMD]  67.55 49.38 90 top
TP87  -  [TP30_SMD]  127.13 48.83 0 top
TP88  -  [TP20_SMD]  67.22 48.09 0 top
TP89  -  [TP30_SMD]  127.43 47.07 0 top
TP90  -  [TP20_SMD]  67.9 47.04 0 top
TP91  -  [TP30_SMD]  126.03 46.64 0 top
TP92  -  [TP20_SMD]  114.35 46.36 270 top
TP93  -  [TP30_SMD]  90.73 46.31 90 top
TP94  -  [TP30_SMD]  111.05 46.03 0 top
TP95  -  [TP30_SMD]  81.89 45.54 90 top
TP96  -  [TP20_SMD]  17.83 37.26 0 top
TP97  -  [TP20_SMD]  27.71 35.88 90 top
TP98  -  [TP30_SMD]  72.74 35.48 90 top
TP99  -  [TP30_SMD]  71.54 33.23 90 top
TP100  -  [TP20_SMD]  71.86 29.65 0 top
TP101  -  [TP20_SMD]  66.2 29.11 0 top
TP102  -  [TP20_SMD]  29.79 28.85 0 top
TP103  -  [TP20_SMD]  50.94 18.06 270 top
TP104  -  [TP20_SMD]  24.03 17.89 90 top
TP105  -  [TP20_SMD]  61.04 16.29 270 top
TP106  -  [TP40_SMD]  14.06 11.73 180 top
TP107  -  [TP20_SMD]  36.05 10.81 90 top
TP108  -  [TP20_SMD]  50.89 9.72 90 top
TP109  -  [TP30_SMD]  114 163.51 0 bottom
TP110  -  [TP30_SMD]  126.59 160.44 0 bottom
TP111  -  [TP30_SMD]  125.25 160.44 0 bottom
TP112  -  [TP30_SMD]  109.19 160.44 0 bottom
TP113  -  [TP30_SMD]  107.85 160.44 0 bottom
TP114  -  [TP30_SMD]  125.93 159.22 0 bottom
TP115  -  [TP30_SMD]  108.79 159.22 0 bottom
TP116  -  [TP20_SMD]  101.04 74.78 270 bottom
TP117  -  [TP20_SMD]  24.05 32.96 0 bottom
U1  SN74LVC1G125DBVR  [SOT23-5]  19.58 174.56 270 top
U2  SN74LVC1G11DRYR  [SON6_SN74LVC2G17_40X60_0-6]  16.38 165.89 90 top
U3  DIX4192IPFB  [TQFP48_19-68_280X280_1-2]  44.76 165.82 0 top
U4  TPS22918DBVR  [SOT23-6]  20.54 165.11 270 top
U5  TAD5212IRGER  [QFN24_TAD5212IRGER_160X160_1]  100.76 164.03 0 top
U6  TAD5212IRGER  [QFN24_TAD5212IRGER_160X160_1]  118.16 164.03 0 top
U7  PCM6240QRTVRQ1  [QFN32_19-68_200X200_0-8_EP3-6]  81.56 160.51 90 top
U8  PCM6240QRTVRQ1  [QFN32_19-68_200X200_0-8_EP3-6]  69.39 159.23 270 top
U9  12.288MHz  [VSON4_LMK6CE_80X100_SMD_1]  38.92 157.16 90 top
U10  TPD6E001RSER  [UQFN10_19-68_80X60_0-6]  19.97 155.38 180 top
U11  TCA9406DCUR  [VSSOP8_19-68_85X95]  128.79 154.1 0 top
U12  TPD2E001DRLR  [SOT553-5_0-6]  28.19 153.9 180 top
U13  SN74LVC1G08DBVRE4  [SOT23-5]  52.66 152.69 90 top
U14  SN74LVC1G08DBVRE4  [SOT23-5]  92.02 149.82 180 top
U15  CDCE6214RGET  [WFQFN24_CDCE6214-Q1_160X160_0-9]  117.47 146.98 270 top
U16  TLV7103318QDSERQ1  [WSON6_TPS717_60X60_0-8]  15.31 146.74 90 top
U17  TCAN3413DR  [SOIC8_1-8]  42.78 146.68 180 top
U18  TCA6416ARTWR  [WQFN24_19-68_160X160]  83.75 145.73 180 top
U19  SN74LVC1G08DBVRE4  [SOT23-5]  29.53 144.12 270 top
U20  SI5351B-B-GM  [QFN20_19-68_160X160_0-9_EP2-7]  73.69 143.94 90 top
U21  TCA6424ARGJR  [QFN32_19-68_200X200]  105.88 142.46 180 top
U22  MCP47CVB02  [DFN10_19-68_120X120_1]  79.02 139.06 90 top
U23  SN74LVC1G08DBVRE4  [SOT23-5]  93.26 132.06 90 top
U24  TXB0102DCUR  [VSSOP8_19-68_85X95_0-9]  56.11 127.81 90 top
U25  TCA9517DR  [SOIC8_1-8]  109.86 128.78 270 top
U26  SN74LVC1G08DBVRE4  [SOT23-5]  63.28 125.55 0 top
U27  SN74LVC1G08DBVRE4  [SOT23-5]  98.76 120.54 0 top
U28  S28HS512TGABHM010  [BGA24_39-37_240X310_1]  78.72 119.91 180 top
U29  SN74AVC2T244DQMR  [X2SON8_15-74_70X50]  72.2 113.04 0 top
U30  SN74LVC1G126DBVR  [SOT23-5_1-5]  52.92 106.12 180 top
U31  SN74LVC1G126DBVR  [SOT23-5_1-5]  57.87 104.29 90 top
U32  TXS0104EPWR  [TSSOP14_25-59_205X180_1-2]  43.63 102.78 0 top
U33  SN74LVC1G126DBVR  [SOT23-5_1-5]  84.63 101.68 0 top
U34  TXS0104EPWR  [TSSOP14_25-59_205X180_1-2]  98.63 101.16 180 top
U35  SN74LVC1G126DBVR  [SOT23-5_1-5]  72.21 101.09 0 top
U36  SN74LVC1G07DBVR  [SOT23-5]  51.63 97.65 180 top
U37  TXB0304RUTR  [UQFN12_15-74_80X70]  24.79 95.1 270 top
U38  TCAN3413DR  [SOIC8_1-8]  38.49 92.26 180 top
U39  TXS0102DQER  [X2SON8_TXS0102_40X60_0-4]  103.35 90.88 90 top
U40  SN74LVC07ADGVR  [TVSOP14_15-74_180X150_1-2]  111.55 88.1 180 top
U41  LM4040B25IDCKR  [SC70-5_1-1]  131.91 86.97 180 top
U42  TPS22965DSGT  [WSON8_19-68_80X80_0-8]  45.72 86.05 90 top
U43  SN74LVC1G11DRYR  [SON6_SN74LVC2G17_40X60_0-6]  101.63 85.76 180 top
U44  TMP100NA/3K  [SOT23-6_1-5]  93.98 85.7 90 top
U45  TXS0104EPWR  [TSSOP14_25-59_205X180_1-2]  20.7 83.44 0 top
U46  TLV75801PDBVT  [SOT23-5_1-5]  41.58 82.34 270 top
U47  XAM62D24AVGHIANF  [FBGA484_31-49_710X710_2-7]  75.56 79.99 90 top
U48  TM4C1294NCPDTT3R  [TQFP128_15-74_550X550_1-2]  125.6 77.1 180 top
U49  MTFC32GAZAQHD-IT  [VFBGA153_19-68_460X520_0-9]  100.6 75.97 90 top
U50  SN74LVC3G17DCUR  [VSSOP8_19-68_85X95_0-9]  29.74 72.02 0 top
U51  TXS0102DQER  [X2SON8_TXS0102_40X60_0-4]  113.75 68.84 180 top
U52  SN74LVC1G11DRYR  [SON6_SN74LVC2G17_40X60_0-6]  25.03 68.64 0 top
U54  SN74LVC1G11DRYR  [SON6_SN74LVC2G17_40X60_0-6]  27.34 66.7 0 top
U55  TPS79601DRBR  [SON8_25-59_130X130_1]  119.44 63.43 270 top
U56  PTPS6522430RAHRQ1  [VQFN-HR36-35_TPS65224_240X200_1]  46.87 62.33 0 top
U57  TMUX154EDGSR  [MSOP10_19-68_120X120_1-1]  25.47 61.86 180 top
U58  MT53E1G32D2FW-046 IT:C  [WFBGA200_MT53E2G32D4DE_400X570_1-2]  75.56 60.83 90 top
U59  TPS7A2118PQWDRBRQ1  [SON8_25-59_130X130_1]  60.87 59.01 270 top
U60  TPD4E004DRYR  [SON6_19-68_40X60_PB_0-6]  128.08 52.05 180 top
U61  93LC46B  [MSOP8_25-59_125X125_1-1]  24.42 51.86 180 top
U62  25.000MHz  [VSON4_LMK6CE_80X100_SMD_1]  78.64 50.46 270 top
U63  TMP100NA/3K  [SOT23-6_1-5]  71.81 49.4 270 top
U64  FT4232HL  [LQFP64_19-68_390X390_1-6]  32.29 43 0 top
U65  LMK1C1103PWR  [TSSOP8_25-59_125X180_1-2]  70.14 41.64 270 top
U66  TPS73533DRVR  [SON6_25-59_85X85]  19.7 38.29 180 top
U67  TPD2E001DRLR  [SOT553-5_0-6]  18.87 31.45 90 top
U68  SN74LVC1G11DRYR  [SON6_SN74LVC2G17_40X60_0-6]  68.7 30.38 0 top
U69  W25Q80DVSNIG  [SOIC8_1-8]  39.57 28.01 0 top
U70  AT24C512C-MAHM-T  [UDFN8_19-68_120X80_0-6]  45.73 27.59 270 top
U71  SN74LVC1G32DPWR  [X2SON5_TLV7021_30X30_0-4]  24.37 24.25 90 top
U72  TPS630702RNMR  [VQFNHR15_TPS630701_100X120_1]  50.84 23.96 0 top
U73  TPS22810DRVT  [SON6_25-59_85X85_0-8]  30.15 21.46 90 top
U74  TPS2051BD  [SOIC8_1-8]  60.7 20.63 270 top
U75  SN74LVC1G08DBVRE4  [SOT23-5]  80.14 172.02 180 bottom
U76  TAD5212IRGER  [QFN24_TAD5212IRGER_160X160_1]  126.18 164.03 180 bottom
U77  TAD5212IRGER  [QFN24_TAD5212IRGER_160X160_1]  108.78 164.03 180 bottom
U78  TXB0304RUTR  [UQFN12_15-74_80X70]  53.35 160.92 0 bottom
U79  TXB0102DCUR  [VSSOP8_19-68_85X95_0-9]  42.66 151.91 90 bottom
U80  SN74AVC4T245RSVR  [UQFN16_TMUX1574_70X100_0-6]  71.64 115.85 0 bottom
U81  SN74AVC8T245RHL  [QFN24_19-68_220X140_1]  114.78 112.39 90 bottom
U82  TCA6424ARGJR  [QFN32_19-68_200X200]  107.26 112.39 180 bottom
U83  SN74AVC8T245RHL  [QFN24_19-68_220X140_1]  98.17 111.73 270 bottom
U84  LCMXO2-256HC-4SG48I  [QFN48_19-68_280X280_1_EP5-4]  78.45 109.79 180 bottom
U85  LCMXO2-256HC-4SG48I  [QFN48_19-68_280X280_1_EP5-4]  65.04 108.4 270 bottom
U86  SN74LVC1G11DRYR  [SON6_SN74LVC2G17_40X60_0-6]  107.6 104.59 270 bottom
U87  SN74LVC1G32DPWR  [X2SON5_TLV7021_30X30_0-4]  111.7 104.42 0 bottom
U88  SN74LVC1G32DPWR  [X2SON5_TLV7021_30X30_0-4]  116.55 102.97 0 bottom
U89  SN74LVC1G126DBVR  [SOT23-5_1-5]  72.24 100.85 0 bottom
U90  SN74AVC2T244DQMR  [X2SON8_15-74_70X50]  113.75 96.82 90 bottom
U91  INA228AIDGSR  [MSOP10_19-68_120X120_1-1]  50.11 89.03 270 bottom
U92  INA231AIYFDR  [DSBGA12_15-74_60X70_0-4]  50.11 89.03 180 bottom
U93  SN74LVC1G04DCKR  [SC70-5]  115.12 84.3 270 bottom
U97  SN74AVC4T245RSVR  [UQFN16_TMUX1574_70X100_0-6]  121.3 81.87 90 bottom
U98  SN74LVC3G17DCUR  [VSSOP8_19-68_85X95_0-9]  31.79 80.8 0 bottom
U102  TXS0102DQER  [X2SON8_TXS0102_40X60_0-4]  121.83 77.91 0 bottom
U107  TCA9517DR  [SOIC8_1-8]  129.34 75.3 270 bottom
U109  SN74AVC2T244DQMR  [X2SON8_15-74_70X50]  120.76 73.11 90 bottom
U110  SN74AVC4T245RSVR  [UQFN16_TMUX1574_70X100_0-6]  124.65 73.06 0 bottom
U113  INA231AIYFDR  [DSBGA12_15-74_60X70_0-4]  37.13 67.93 0 bottom
U114  INA228AIDGSR  [MSOP10_19-68_120X120_1-1]  37.13 67.93 90 bottom
U115  INA231AIYFDR  [DSBGA12_15-74_60X70_0-4]  56.06 57.55 0 bottom
U116  INA228AIDGSR  [MSOP10_19-68_120X120_1-1]  56.06 57.55 90 bottom
U117  SN74AVC4T245RSVR  [UQFN16_TMUX1574_70X100_0-6]  32.96 56.47 270 bottom
U118  INA228AIDGSR  [MSOP10_19-68_120X120_1-1]  58.69 48.94 90 bottom
U119  INA231AIYFDR  [DSBGA12_15-74_60X70_0-4]  58.69 48.94 0 bottom
U120  SN74LVC1G11DRYR  [SON6_SN74LVC2G17_40X60_0-6]  113.17 47.55 180 bottom
U121  INA231AIYFDR  [DSBGA12_15-74_60X70_0-4]  53.22 44.01 0 bottom
U122  INA228AIDGSR  [MSOP10_19-68_120X120_1-1]  53.22 44.01 90 bottom
U123  INA231AIYFDR  [DSBGA12_15-74_60X70_0-4]  47.86 42.93 0 bottom
U124  INA228AIDGSR  [MSOP10_19-68_120X120_1-1]  47.86 42.93 90 bottom
U125  SN74AVC4T245RSVR  [UQFN16_TMUX1574_70X100_0-6]  30.24 41.2 0 bottom
U126  SN74AVC4T245RSVR  [UQFN16_TMUX1574_70X100_0-6]  28.27 33.96 90 bottom
U127  TPS62824DMQR  [VSONHR6_TPS62826_60X60_1]  91.66 31.55 0 bottom
U128  LM5141QRGETQ1  [VQFN24_LM5141_160X160_1]  19.66 21.95 270 bottom
U129  TPS65988DHRSHR  [VQFN56_TPS65987D_280X280_1]  40.05 20.38 90 bottom
U130  TPD4S012DRYR  [SON6_SN74LVC2G17_40X60_0-6]  64.81 16.91 90 bottom
U131  CSD17308Q3  [VSON8_CSD173_130X130]  20.54 13.08 180 bottom
U132  TVS2200DRVR  [SON6_25-59_85X85_0-8]  52.31 10.33 180 bottom
U133  TVS2200DRVR  [SON6_25-59_85X85_0-8]  34.52 9.36 270 bottom
Y1  24.576MHz  [XTAL4_ABMM_280X200_SMD_1-3]  118.56 155.86 0 top
Y2  27.000MHz  [XTAL4_ABM8_130X110_0-8_SMD]  72.88 136.77 0 top
Y3  25.000MHz  [XTAL4_XRCGB-FM_80X60_SMD_0-7]  55.49 80.77 270 top
Y4  32.768KHz  [XTAL_ECS-32_130X60_SMD_0-9]  56.61 75.8 90 top
Y5  16.000MHz  [XTAL4_XRCGB-FM_80X60_SMD_0-7]  114.33 73.85 90 top
Y6  12.000MHz  [XTAL_ABM3_205X130_SMD_1-4]  21.53 46.8 270 top

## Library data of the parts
C1-C8 C10-C195 C197 C199-C209 C211-C213 C215-C314 C316-C327 C329-C421 C423-C441 C443-C480 C483-C644 C646-C656 = CAP
C9 C315 C328 C645 = CAP_POL
C196 C198 C210 C214 C422 C442 C481 C482 C657-C670 = FILTER3_NFM18
D1 D3 D10-D14 = DIODE_SOD323
D2 D4 D6 = DIODE_ZENER_SOT23_13
D5 = DIODE_BAT54CW_SOT323-123
D7 D8 D16 D17 = DIODE_TVS_DUAL
D9 = DIODE_ESD122DMXR
D15 = DIODE_SCHOTTKY
FL1-FL18 = EMIFILTER_IND
J1-J4 = CON_AUDIOJACK6_STX-4235-3/3
J5 J6 = CON_RCAJACK3_RCJ-02X
J7 J10 J16 J20 = HEADER_2X1
J8 J11 = HEADER_6X1
J9 J15 = HEADER_3X1
J12 J13 = CON40X2_SAMTEC
J14 = HEADER_10X2_FTR-06
J17 J22 = CON_USB_MINI-B
J18 J19 = CON_BTOB_24X2_M_SH4
J21 = HEADER_5X2
J23 = CON_USB-A_4_2SH
J24 J25 = CON_USB-C_24_1240183621
J26 = CON_SDCARD9_MEM2075-00-140
L1-L8 L11 L12 = INDUCTOR
L9 = INDUCTOR_DLW31S: signal model: INDUCTOR_DLW31S_IND4_DLW21H_90X_90E
L10 = INDUCTOR_DLW31S
LD1-LD10 = DIODE_LED
MOD1 = MODULE_PLR135T10
Q1 Q5 Q10 = MOSFET_CSD17313Q2
Q2 = NPN_123_SOT23-3
Q3 Q4 = MOSFET_BSS138W
Q6 Q7 = MOSFET_IRLML6401TR
Q8 Q9 = MOSFET_CSD25310Q2
Q11 = MOSFET_CSD17301Q5A
R1-R72 R75-R86 R88 R90-R94 R96-R98 R102 R103 R106-R108 R110-R175 R178-R189 R194-R196 R198-R200 R202-R205 R208 R210-R227 R229-R238 R240-R250 R252-R260 R262-R264 R266-R315 R317-R326 R328-R333 R335-R452 R454-R462 R464-R473 R476 R480-R490 R496 R503-R505 R507 R508 R510-R517 R519-R526 R531-R534 R536 R539-R557 R559-R580 R582-R683 = RESISTOR
R73 R74 R87 R89 R95 R99-R101 R104 R105 R109 R453 R463 R474 R475 R477-R479 R538 R558 = RESISTOR: signal model: RESISTOR_RES0201_0-5_22E_1%_22E_1%
R176 R177 R190-R193 R201 R206 R207 R209 R228 R239 R261 R491-R495 R497-R502 R506 R509 R518 R527-R530 R535 R537 = RESISTOR: signal model: RESISTOR_RES0201_0-5_0E_0E
R197 = RESISTOR: signal model: RESISTOR_RES0402_0-5_0E_0E
R251 R265 R316 R327 R334 R581 = RESISTOR-4TERM
RA1 RA2 = RESARR_ISO2
RA3 RA4 = RESARR_ISO4: signal model: RESARR_ISO4_RESA_EXB_0201-4_0-5_0E
RA5-RA7 = RESARR_ISO4
SW1 SW2 = SW16_CHS-08A
SW3 = SW4_GDH02S04
SW4-SW8 = 7914G-1-000E _7914G
TP1-TP117 = TESTPOINT
U1 = SN74LVC1G125_SOT23-5
U2 U43 U52 U54 U68 U86 U120 = SN74LVC1G11DCKR_SC70-6
U3 = DIX4192IPFB_TQFP48
U4 = TPS22918DBVR_SOT23-6
U5 U6 U76 U77 = TAD5212IRGER_QFN24
U7 U8 = PCM6240QRTVRQ1_WQFN32
U9 U62 = OSC4_LMK6CE
U10 = TPD6E001RSE_UQFN10
U11 = TCA9406DCUR_VSSOP8
U12 U67 = TPD2E001DRLR_SOT-5
U13 U14 U19 U23 U26 U27 U75 = SN74LVC1G08DBVRE4_SOT23-5
U15 = CDCE6214_WFQFN24
U16 = TLV7103318D_WSON6
U17 U38 = TCAN3413DR_SOIC8
U18 = TCA6416ARTWR_WQFN24
U20 = SI5351B_QFN20
U21 U82 = TCA6424ARGJR_QFN32
U22 = MCP47CXBX2_DFN10
U24 U79 = TXB0102DCUR_US8
U25 U107 = TCA9517DGKR_VSSOP8
U28 = S28HS512T_BGA24
U29 U90 U109 = SN74AVC2T244DQMR_X2SON8
U30 U31 U33 U35 U89 = SN74LVC1G126DBVR_SOT23-5
U32 U34 U45 = TXS0104EPWR_TSSOP14
U36 = SN74LVC1G07DBVR_SOT23-5
U37 U78 = TXB0304RUTR_QFN12
U39 U51 U102 = TXS0102DQX_SON8
U40 = 74HC7014X_SOIC14
U41 = LM4040B25IDCKR_SC70-5
U42 = TPS22965DSGT_WSON8
U44 U63 = TMP100NA/3K_SOT23-6
U46 = TLV75801P_SOT23-5
U47 = AM62D_EVM_SOC_FCBGA484
U48 = TM4C1294NCPDTT3R_TQFP128
U49 = MTFC16GAPALBH_TFBGA153
U50 U98 = SN74LVC3G17DCUR_VSSOP8
U55 = TPS79601DRBR_SON8
U56 = TPS65224_VQFN-HR36
U57 = TMUX154EDGSR_VSSOP10
U58 = MT53D1024M32D4DT_VFBGA200
U59 = TPS7A21_SON8
U60 = TPD4E004_SON6
U61 = 93LC46B_MSOP8
U64 = FT4232H_LQFP64
U65 = LMK1C1103_TSSOP8
U66 = TPS73501DRVR_SON6
U69 = W25Q80BWSNIG_SOIC8
U70 = AT24C64D-MAHM-T_UDFN8
U71 U87 U88 = SN74LVC1G32_X2SON5
U72 = TPS630701_VQFN-HR15
U73 = TPS22810DRVT_WSON6
U74 = TPS2051BD_SOIC8
U80 U97 U110 U117 U125 U126 = SN74AVC4T245RSV_UQFN16
U81 U83 = SN74AVC8T245RHL_QFN24
U84 U85 = LCMXO2-256HC_VFQFN48
U91 U114 U116 U118 U122 U124 = INA226AIDGS_MSOP10
U92 U113 U115 U119 U121 U123 = INA231_DSBGA12
U93 = SN74LVC1G04DCKR_SC70-5
U127 = TPS62827DMQR_VSONHR6
U128 = LM5141RGET_VQFN24
U129 = TPS65988DJ_VQFN56
U130 = TPD4S012DRY_SON6
U131 = MOSFET_CSD18501Q5A
U132 U133 = TVS2200_WSON6
Y1 = CRY4_ABMM
Y2 = CRY4_ABM8
Y3 Y5 = CRY4_13
Y4 Y6 = CRY

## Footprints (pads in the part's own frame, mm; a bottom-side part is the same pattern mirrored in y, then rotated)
BGA24_39-37_240X310_1
  round 0.356 smd: A2(-1,2) A3(0,2) A4(1,2) A5(2,2) B1(-2,1) B2(-1,1) B3(0,1) B4(1,1) B5(2,1) C1(-2,0) C2(-1,0) C3(0,0) C4(1,0) C5(2,0) D1(-2,-1) D2(-1,-1) D3(0,-1) D4(1,-1) D5(2,-1) E1(-2,-2) E2(-1,-2) E3(0,-2) E4(1,-2) E5(2,-2)
CAP0201_0-5
  rect 0.356x0.33 smd: 1(-0.28,0) 2(0.28,0)
CAP0201_0-75
  rect 0.457x0.432 smd: 1(-0.34,0) 2(0.34,0)
CAP0402_0-75
  rect 0.559x0.635 smd: 1(-0.49,0) 2(0.49,0)
CAP0402_1
  rect 0.559x0.635 smd: 1(-0.49,0) 2(0.49,0)
CAP0603_1
  rect 0.94x1.016 smd: 1(-0.8,0) 2(0.8,0)
CAP0805_1-5
  rect 0.94x1.346 smd: 1(-0.8,0) 2(0.8,0)
CAP1206_1-75
  rect 1.143x1.803 smd: 1(-1.5,0) 2(1.5,0)
CAP1206_2
  rect 1.143x1.803 smd: 1(-1.5,0) 2(1.5,0)
CAP1210_2-75
  rect 0.94x2.591 smd: 1(-1.4,0) 2(1.4,0)
CAPAE_FCASE_10-5
  rect 4.191x2.108 smd: 1(-3.7,0) 2(3.7,0)
CAPCT0805H_1
  rect 0.66x1.549 smd: 1(-1.15,0) 2(1.15,0)
CAPT7343D_3-25
  rect 2.362x2.438 smd: 1(-3.1,0) 2(3.1,0)
CON_40X2_QSE-040-01_S_S_S
  round 0.889 hole 1.016 unplated: (-20.07,2.665) (20.07,2.665)
  rect 0.406x2.286 smd: 1(-17.6,-2.865) 2(-17.6,2.865) 3(-16.8,-2.865) 4(-16.8,2.865) 5(-16,-2.865) 6(-16,2.865) 7(-15.2,-2.865) 8(-15.2,2.865) 9(-14.4,-2.865) 10(-14.4,2.865) 11(-13.6,-2.865) 12(-13.6,2.865) 13(-12.8,-2.865) 14(-12.8,2.865) 15(-12,-2.865) 16(-12,2.865) 17(-11.2,-2.865) 18(-11.2,2.865) 19(-10.4,-2.865) 20(-10.4,2.865) 21(-9.6,-2.865) 22(-9.6,2.865) 23(-8.8,-2.865) 24(-8.8,2.865) 25(-8,-2.865) 26(-8,2.865) 27(-7.2,-2.865) 28(-7.2,2.865) 29(-6.4,-2.865) 30(-6.4,2.865) 31(-5.6,-2.865) 32(-5.6,2.865) 33(-4.8,-2.865) 34(-4.8,2.865) 35(-4,-2.865) 36(-4,2.865) 37(-3.2,-2.865) 38(-3.2,2.865) 39(-2.4,-2.865) 40(-2.4,2.865) 41(2.4,-2.865) 42(2.4,2.865) 43(3.2,-2.865) 44(3.2,2.865) 45(4,-2.865) 46(4,2.865) 47(4.8,-2.865) 48(4.8,2.865) 49(5.6,-2.865) 50(5.6,2.865) 51(6.4,-2.865) 52(6.4,2.865) 53(7.2,-2.865) 54(7.2,2.865) 55(8,-2.865) 56(8,2.865) 57(8.8,-2.865) 58(8.8,2.865) 59(9.6,-2.865) 60(9.6,2.865) 61(10.4,-2.865) 62(10.4,2.865) 63(11.2,-2.865) 64(11.2,2.865) 65(12,-2.865) 66(12,2.865) 67(12.8,-2.865) 68(12.8,2.865) 69(13.6,-2.865) 70(13.6,2.865) 71(14.4,-2.865) 72(14.4,2.865) 73(15.2,-2.865) 74(15.2,2.865) 75(16,-2.865) 76(16,2.865) 77(16.8,-2.865) 78(16.8,2.865) 79(17.6,-2.865) 80(17.6,2.865)
  rect 2.794x0.432 smd: 81(-18.07,-0.005) 84(-1.94,-0.005) 85(1.93,-0.005) 88(18.06,-0.005)
  rect 4.724x0.432 smd: 82(-13.18,-0.005) 83(-6.83,-0.005) 86(6.82,-0.005) 87(13.17,-0.005)
CON_AV6_STX-4235-3-3_S_R_T_26
  oval 1.854x3.886 hole 1.981x4.013 unplated: (-7,0) (-3,0)
  rect 2.21x2.21 hole 1.524: 1A(0,0)
  round 2.21 hole 1.524: 1B(-10,0) 2A(1.25,7.5) 2B(-10,5) 5A(-11.25,7.5) 5B(0,5)
CON_BTOB2X24_DF40GB-48DP_P_S_S_1-3
  rect 0.229x0.66 smd: 1(-4.6,-1.355) 2(-4.6,1.355) 3(-4.2,-1.355) 4(-4.2,1.355) 5(-3.8,-1.355) 6(-3.8,1.355) 7(-3.4,-1.355) 8(-3.4,1.355) 9(-3,-1.355) 10(-3,1.355) 11(-2.6,-1.355) 12(-2.6,1.355) 13(-2.2,-1.355) 14(-2.2,1.355) 15(-1.8,-1.355) 16(-1.8,1.355) 17(-1.4,-1.355) 18(-1.4,1.355) 19(-1,-1.355) 20(-1,1.355) 21(-0.6,-1.355) 22(-0.6,1.355) 23(-0.2,-1.355) 24(-0.2,1.355) 25(0.2,-1.355) 26(0.2,1.355) 27(0.6,-1.355) 28(0.6,1.355) 29(1,-1.355) 30(1,1.355) 31(1.4,-1.355) 32(1.4,1.355) 33(1.8,-1.355) 34(1.8,1.355) 35(2.2,-1.355) 36(2.2,1.355) 37(2.6,-1.355) 38(2.6,1.355) 39(3,-1.355) 40(3,1.355) 41(3.4,-1.355) 42(3.4,1.355) 43(3.8,-1.355) 44(3.8,1.355) 45(4.2,-1.355) 46(4.2,1.355) 47(4.6,-1.355) 48(4.6,1.355)
  rect 0.356x0.711 smd: SH1(-5.135,-0.86) SH2(-5.135,0.86) SH3(5.135,-0.86) SH4(5.135,0.86)
CON_MUSBB5_629105150521_S_R_S_2-7
  round 0.686 hole 0.813 unplated: (-2.5,1.848) (2.5,1.848)
  rect 0.457x1.295 smd: 1(-1.3,2.948) 2(-0.65,2.948) 3(0,2.948) 4(0.65,2.948) 5(1.3,2.948)
  oval 1.448x2.311 hole 0.864x1.727: 6(-3.725,2.898) 7(3.725,2.898)
  oval 1.143x1.803 hole 0.559x1.219: 8(-3.875,-0.902) 9(3.875,-0.902)
